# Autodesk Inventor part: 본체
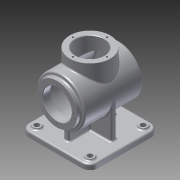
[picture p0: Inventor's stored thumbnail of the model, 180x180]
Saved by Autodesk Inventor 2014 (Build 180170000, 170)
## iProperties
Created: 2015-07
Part Number: 본체
Material: 알루미늄 6061
Document SubType Name: Modeling
Designer: 704_05
Density: 2.71 g/cm^3
Appearance: 알루미늄 - 평지
Mass: 1277.8 g
Surface Area: 1267.53 cm^2
Volume: 471.512 cm^3
Author: 704_05
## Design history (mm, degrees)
sketch "스케치1"
  geometry: L1 (0, 62)-(0, -55); L2 (0, 62)-(-38, 62); L3 (-38, 62)-(-38, 58); L4 (-41, 55)-(-42, 55); L5 (-45, 52)-(-45, -52); L6 (-42, -55)-(0, -55); A1 r 3 centre (-41, 58) between (-41, 55) and (-38, 58); A2 r 3 centre (-42, 52) between (-42, 55) and (-45, 52); A3 r 3 centre (-42, -52) between (-45, -52) and (-42, -55); 3 further points
  constraints: 12 end point, 6 point on circle, 6 tangent, 4 point on line, 3 centre point, 3 parallel, 2 equal radius, 2 perpendicular, 1 vertical, 1 vertical alignment
  dimensions: "d6" = 117 distance of L1.start L1.end; "d7" = 55 distance of L1.end point (0, 0); "d8" = 7 distance of L2.end point (-38, 55); "d9" = 76 diameter of L2.end L1; "d10" = 90 diameter of point (-45, 55) L1; "d11" = 3 radius of A1
revolve "회전1" sketch "스케치1" stored, may be unused: angle "d12" = 90 deg
hole "구멍1" diameter "d15" = 54; stored, may be unused: countersink angle "d19" = 90 deg, drill point angle "d21" = 0 deg; dims "d13" = 10, "d14" = 10, "d16" = 6, "d17" = 4, "d18" = 2, "d20" = 14
hole "구멍2" diameter "d24" = 80; stored, may be unused: countersink angle "d28" = 90 deg, drill point angle "d30" = 0 deg; dims "d22" = 10, "d23" = 10, "d25" = 6, "d26" = 4, "d27" = 2, "d29" = 96
fillet "모깎기1" dims "d31" = 3
node "작업 평면1"
sketch "스케치2"
  geometry: L1 (50, -65)-(-50, -65); L2 (-65, -50)-(-65, 50); L3 (-50, 65)-(50, 65); L4 (65, 50)-(65, -50); A1 r 15 centre (50, -50) between (50, -65) and (65, -50); A2 r 15 centre (-50, -50) between (-65, -50) and (-50, -65); A3 r 15 centre (-50, 50) between (-50, 65) and (-65, 50); A4 r 15 centre (50, 50) between (65, 50) and (50, 65); 4 further points
  constraints: 8 end point, 8 point on circle, 8 tangent, 6 point on line, 4 centre point, 3 equal radius, 2 parallel, 1 horizontal, 1 perpendicular
  dimensions: "d33" = 130 distance of point (-65, 65) point (65, 65); "d34" = 130 distance of point (-65, -65) point (-65, 65); "d35" = 65 distance from line of L3 point (0, 0); "d36" = 65 distance from line of point (0, 0) L4; "d37" = 15 radius of A1
extrude "돌출1" join sketch "스케치2" distance "d38" = 10; taper "d39" = 0 deg
sketch "스케치3"
  geometry: C1 r 7.5 at (-50, 50); C2 r 7.5 at (-50, -50); C3 r 7.5 at (50, -50); C4 r 7.5 at (50, 50); 1 further point
  constraints: 4 centre point, 2 horizontal alignment, 2 vertical alignment
  dimensions: "d40" = 15 diameter of C1; "d41" = 15 diameter of C2; "d42" = 15 diameter of C3; "d43" = 15 diameter of C4; "d44" = 100 distance of C2.centre C1.centre; "d45" = 100 distance of C1.centre C4.centre; "d46" = 50 horizontal distance of point (0, 0) C1.centre; "d47" = 50 horizontal distance of point (0, 0) C1.centre
extrude "돌출2" join sketch "스케치3" distance "d48" = 3; taper "d49" = 0 deg
fillet "모깎기2" dims "d50" = 3
fillet "모깎기3" dims "d51" = 3
sketch "스케치4"
  geometry: L1 (50, -62)-(-50, -62) reference; L2 (-5, 42)-(-5, 5); L3 (-5, 5)-(-42, 5); L4 (-45, 2)-(-45, -2); L5 (-42, -5)-(-5, -5); L6 (-5, -5)-(-5, -42); L7 (-2, -45)-(2, -45); L8 (5, -42)-(5, -5); L9 (5, -5)-(42, -5); L10 (45, -2)-(45, 2); L11 (42, 5)-(5, 5); L12 (5, 5)-(5, 42); L13 (2, 45)-(-2, 45); A1 r 3 centre (-2, 42) between (-2, 45) and (-5, 42); A2 r 3 centre (2, 42) between (5, 42) and (2, 45); A3 r 3 centre (42, 2) between (45, 2) and (42, 5); A4 r 3 centre (42, -2) between (42, -5) and (45, -2); A5 r 3 centre (2, -42) between (2, -45) and (5, -42); A6 r 3 centre (-2, -42) between (-5, -42) and (-2, -45); A7 r 3 centre (-42, -2) between (-45, -2) and (-42, -5); A8 r 3 centre (-42, 2) between (-42, 5) and (-45, 2); 13 further points
  constraints: 24 end point, 16 point on circle, 16 point on line, 16 tangent, 8 centre point, 8 parallel, 7 equal radius, 4 midpoint, 2 collinear, 2 horizontal alignment, 2 perpendicular, 2 vertical alignment
  dimensions: "d52" = 10 distance of point (45, -5) point (45, 5); "d53" = 10 distance of point (5, 45) point (-5, 45); "d54" = 10 distance of point (-45, 5) point (-45, -5); "d55" = 10 distance of point (-5, -45) point (5, -45); "d56" = 90 distance between parallel lines of L7 L13; "d57" = 90 distance between parallel lines of L10 L4; "d58" = 45 distance from line of point (0, 0) L7; "d59" = 45 distance from line of point (0, 0) L4; "d60" = 3 radius of A1
extrude "돌출3" join sketch "스케치4" stored distance "d61" = 10; taper "d62" = 0 deg
fillet "모깎기4" dims "d63" = 3
sketch "스케치5"
  geometry: C1 r 7.5 at (0, 0) reference; C2 r 7.5 at (0, 100) reference; C3 r 7.5 at (-100, 100) reference; C4 r 7.5 at (-100, 0) reference; 5 further points
  constraints: 4 coincident
hole "구멍3" sketch "스케치5" at (-100, 100), (0, 100), (0, 0), (-100, 0) diameter "d64" = 10; stored, may be unused: countersink angle "d68" = 90 deg, drill point angle "d70" = 118 deg; dims "d65" = 6, "d66" = 4, "d67" = 2, "d69" = 8
fillet "모깎기5" dims "d71" = 3
node "작업 평면2"
sketch "스케치6"
  geometry: C1 r 38 at (0, 0); 1 further point
  constraints: 1 centre point, 1 coincident
  dimensions: "d73" = 76 diameter of C1
extrude "돌출4" join sketch "스케치6" stored distance "d74" = 10; taper "d75" = 0 deg
fillet "모깎기6" dims "d76" = 3
hole "구멍4" diameter "d79" = 54; stored, may be unused: countersink angle "d83" = 90 deg, drill point angle "d85" = 0 deg; dims "d77" = 10, "d78" = 10, "d80" = 6, "d81" = 4, "d82" = 2, "d84" = 8
chamfer "모따기1" distance "d86" = 1; stored, may be unused: second distance "d87" = 2, angle "d88" = 45 deg
sketch "스케치7"
  geometry: C1 r 38 at (0, 0) reference; 4 further points
  constraints: 3 vertical alignment, 2 horizontal alignment
  dimensions: "d89" = 64 distance of point (32, 0) point (-32, 0); "d90" = 64 distance of point (0, 32) point (0, -32); "d91" = 32 distance of C1.centre point (0, 32); "d92" = 32 distance of C1.centre point (-32, 0)
hole "구멍5" sketch "스케치7" at (0, 32), (32, 0), (-32, 0), (0, -32) diameter "d93" = 3.242; stored, may be unused: countersink angle "d97" = 90 deg, drill point angle "d99" = 0 deg; dims "d94" = 8, "d95" = 4, "d96" = 2, "d98" = 10
sketch "스케치8"
  geometry: C1 r 38 at (0, 0) reference; 4 further points
  constraints: 2 horizontal alignment, 2 vertical alignment
  dimensions: "d100" = 64 distance of point (32, 0) point (-32, 0); "d101" = 64 distance of point (0, 32) point (0, -32); "d102" = 32 distance of C1.centre point (-32, 0); "d103" = 32 distance of C1.centre point (0, 32)
hole "구멍6" sketch "스케치8" at (0, 32), (0, -32), (-32, 0), (32, 0) diameter "d104" = 3.242; stored, may be unused: countersink angle "d108" = 90 deg, drill point angle "d110" = 0 deg; dims "d105" = 8, "d106" = 4, "d107" = 2, "d109" = 10
node "작업 평면3"
sketch "스케치10"
  geometry: 1 further point
  constraints: 1 other
feature "엠보싱1" sketch "스케치10" dims "d6" = 117, "d7" = 55, "d8" = 7, "d9" = 76, "d10" = 90, "d11" = 3, "d112" = 0.5, "d113" = 0
node "솔리드1"
other parameters: "d32" = -78, "d72" = 62, "d111" = 55.5625
